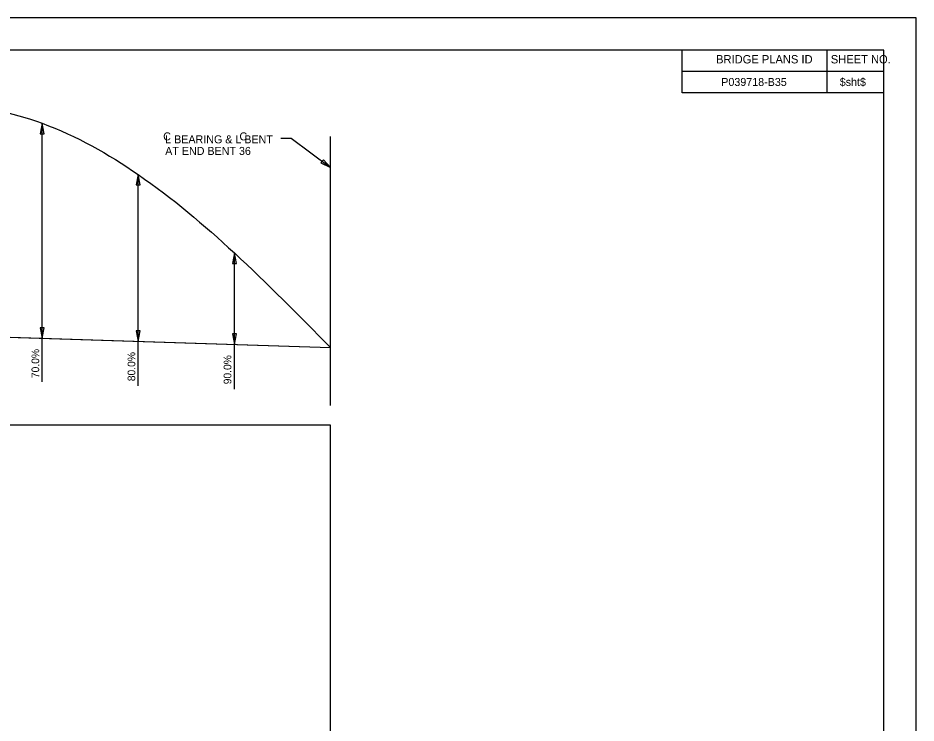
# Model space of a CAD drawing. Extents: x -133.1 to -97, y -1.7 to 20.3.
# Drawn here: x -111.16 to -97.14, y 9.31 to 20.31 of the extents above; entities that cross this region are included whole.
import ezdxf

# ---------------------------------------------------------------- set-up
doc = ezdxf.new("R2010")
doc.units = 0
for name, color, linetype in [('BR_AUTO DIMENSION', 7, 'Continuous'), ('BR_BORDER LINES', 7, 'Continuous'), ('BR_CENTER LINES', 7, 'Continuous'), ('BR_TABLE LINES', 7, 'Continuous'), ('BR_TEXT', 7, 'Continuous'), ('Default', 7, 'Continuous'), ('Level 31', 7, 'Continuous')]:
    doc.layers.add(name, color=color, linetype=linetype)

msp = doc.modelspace()

# ---------------------------------------------------------------- linework, layer by layer
at = {"layer": 'BR_AUTO DIMENSION'}
for p, q in [((-107.057, 18.433), (-106.896, 18.433)), ((-106.896, 18.433), (-106.284, 17.974))]:
    msp.add_line(p, q, dxfattribs=at)
for points in [[(-110.753, 18.504), (-110.784, 18.666), (-110.815, 18.504)], [(-106.432, 18.048), (-106.284, 17.974), (-106.394, 18.098)], [(-109.253, 17.704), (-109.284, 17.866), (-109.315, 17.704)], [(-107.753, 16.481), (-107.784, 16.643), (-107.815, 16.481)], [(-110.815, 15.475), (-110.784, 15.313), (-110.753, 15.475)], [(-109.315, 15.427), (-109.284, 15.264), (-109.253, 15.427)], [(-107.815, 15.379), (-107.784, 15.217), (-107.753, 15.379)], [(-124.284, 1.983), (-106.284, 1.983), (-106.284, 13.956), (-124.284, 13.956)]]:
    msp.add_lwpolyline(points, close=True, dxfattribs=at)
at = {"layer": 'BR_BORDER LINES'}
for p, q in [((-97.642, 19.809), (-131.308, 19.809)), ((-100.794, 19.142), (-100.794, 19.809)), ((-98.528, 19.142), (-98.528, 19.809)), ((-97.642, -1.191), (-97.642, 19.809)), ((-100.794, 19.479), (-97.642, 19.479)), ((-98.528, 19.479), (-97.642, 19.479)), ((-97.642, 19.142), (-100.794, 19.142))]:
    msp.add_line(p, q, dxfattribs=at)
at = {"layer": 'BR_CENTER LINES'}
msp.add_line((-106.284, 14.261), (-106.284, 18.461), dxfattribs=at)
at = {"layer": 'BR_TABLE LINES'}
for p, q in [((-110.784, 14.632), (-110.784, 18.666)), ((-109.284, 14.57), (-109.284, 17.866)), ((-107.784, 14.518), (-107.784, 16.643)), ((-121.285, 15.65), (-106.284, 15.168))]:
    msp.add_line(p, q, dxfattribs=at)
msp.add_spline([(-121.285, 15.65), (-119.785, 15.849), (-118.285, 16.413), (-117.393, 16.914), (-116.784, 17.256), (-115.284, 18.119), (-113.784, 18.746), (-112.284, 18.958), (-110.784, 18.666), (-109.284, 17.866), (-107.784, 16.643), (-106.284, 15.168)], degree=3, dxfattribs=at)
at = {"layer": 'Default'}
msp.add_lwpolyline([(-121.285, 15.65), (-106.284, 15.168)], dxfattribs=at)
at = {"layer": 'Level 31'}
msp.add_lwpolyline([(-133.141, -1.691), (-97.141, -1.691), (-97.141, 20.309), (-133.141, 20.309)], close=True, dxfattribs=at)

# ---------------------------------------------------------------- texts
at = {"layer": 'BR_AUTO DIMENSION'}
for s, p in [('C', (-108.895, 18.399)), ('C', (-107.704, 18.399)), ('L BEARING & L BENT', (-108.864, 18.353)), ('AT END BENT 36', (-108.864, 18.172))]:
    msp.add_text(s, height=0.125, dxfattribs=at).set_placement(p)
at = {"layer": 'BR_TEXT'}
for s, height, p in [('BRIDGE PLANS ID', 0.13, (-100.263, 19.6)), ('SHEET NO.', 0.13, (-98.472, 19.6)), ('P039718-B35', 0.125, (-100.182, 19.248)), ('$sht$', 0.125, (-98.332, 19.248))]:
    msp.add_text(s, height=height, dxfattribs=at).set_placement(p)
for s, p in [('70.0%', (-110.831, 14.69)), ('80.0%', (-109.331, 14.642)), ('90.0%', (-107.831, 14.594))]:
    msp.add_text(s, height=0.12, rotation=90, dxfattribs=at).set_placement(p)

doc.saveas('drawing.dxf')
